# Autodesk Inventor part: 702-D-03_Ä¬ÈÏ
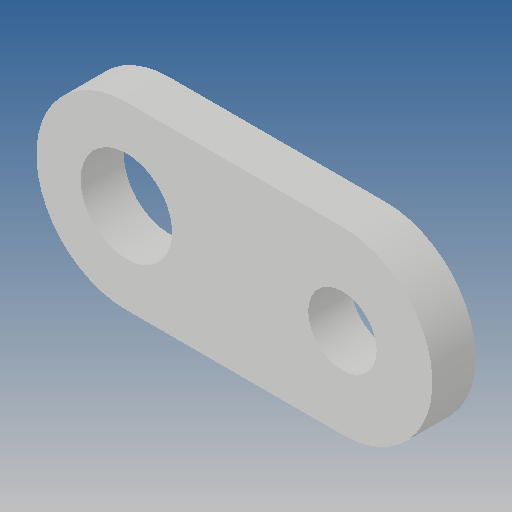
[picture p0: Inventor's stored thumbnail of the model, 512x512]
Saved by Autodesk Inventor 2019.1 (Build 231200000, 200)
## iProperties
Created: 2010-06
Part Number: 702-D-03_Ä¬ÈÏ
Material: Ogólny
Document SubType Name: Modeling
Designer: CADENGINEERING4
Density: 1 g/cm^3
Appearance: Domyślna
Author: CADENGINEERING4
Revision Number: ÈÎºÎ
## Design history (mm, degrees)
feature "NONE"
node "Bryła1"
